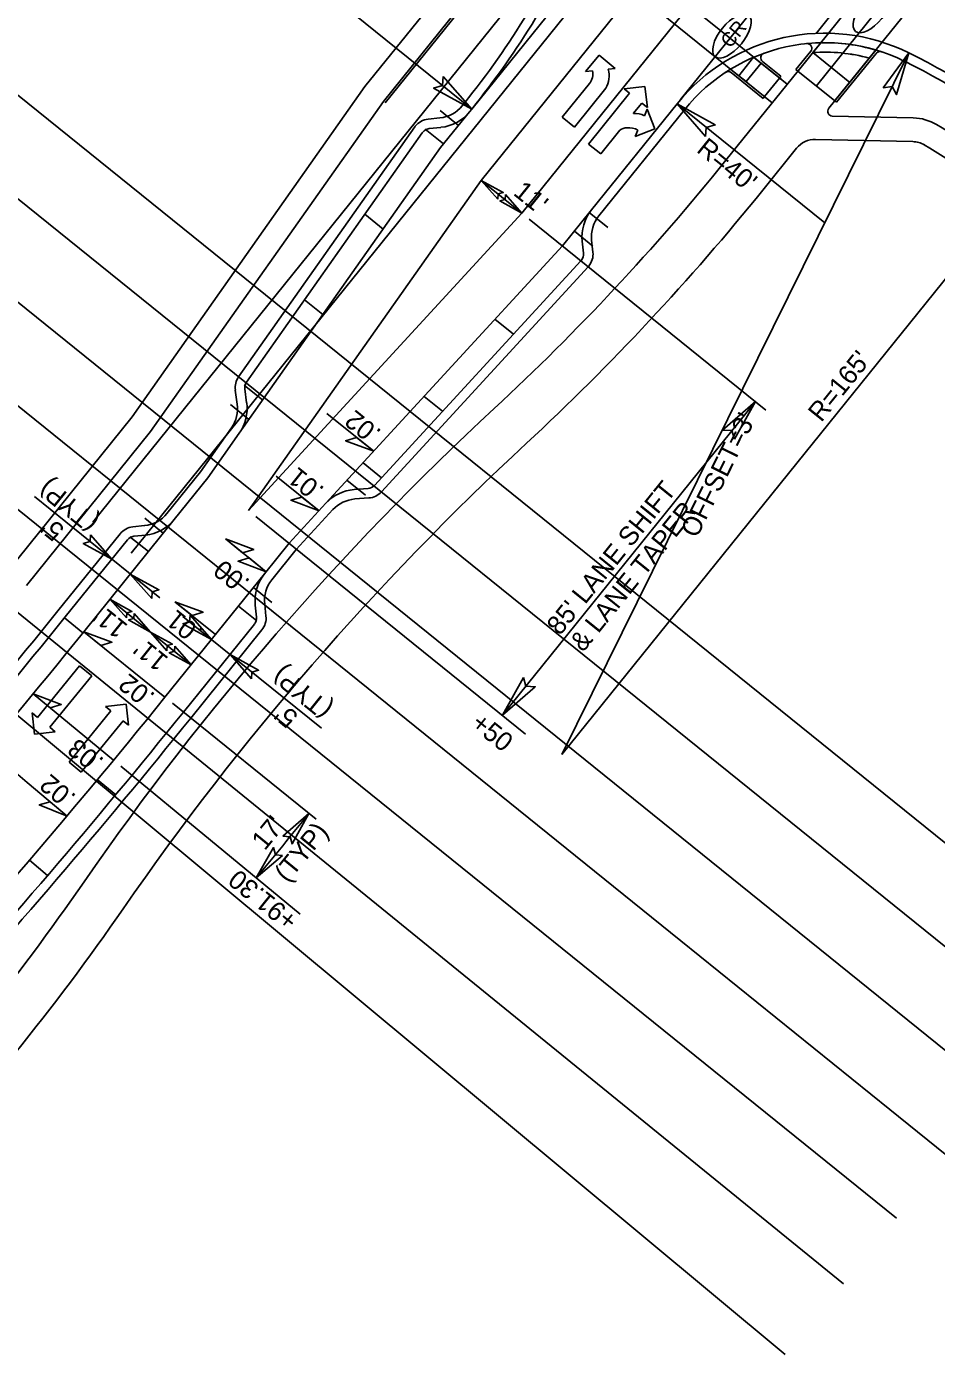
# Model space of a CAD drawing. Extents: x 1486489 to 1490134, y 497089 to 500876.
# Drawn here: x 1488552.5 to 1488744.4, y 498768.4 to 499048.4 of the extents above; entities that cross this region are included whole.
import ezdxf

# ---------------------------------------------------------------- set-up
doc = ezdxf.new("R2010")
doc.units = 0
for name, color, linetype in [('DEV PRELIMINARY STAMP CELL', 7, 'Continuous'), ('Gray Area Fill Shapes', 7, 'Continuous'), ('Pattern 5', 7, 'Continuous'), ('Prop DSN Text', 7, 'Continuous'), ('Prop Horizontal Alignment Station Label', 7, 'Continuous'), ('Prop North Arrow NAD83 for Plan Sheets CELL', 7, 'Continuous'), ('Prop Text', 7, 'Continuous'), ('Prop WCC CELL', 7, 'Continuous'), ('Scratch_Level_0', 7, 'Continuous'), ('Scratch_Level_5', 7, 'Continuous'), ('Sheet Block Revision CELL', 7, 'Continuous'), ('Sheet Block Title CELL', 7, 'Continuous'), ('Sheet Border Standard 30in CELL', 7, 'Continuous'), ('Sheet Cutting Line CELL', 7, 'Continuous'), ('Sheet Data Field CELL', 7, 'Continuous'), ('Sheet Plan CELL', 7, 'Continuous'), ('Sheet Plot Border Inside CELL', 7, 'Continuous'), ('Sheet Plot Border Outside CELL', 7, 'Continuous'), ('Sheet Sticker Exception Certification CELL', 7, 'Continuous'), ('Sheet Title CELL', 7, 'Continuous')]:
    doc.layers.add(name, color=color, linetype=linetype)

msp = doc.modelspace()

# ---------------------------------------------------------------- linework, layer by layer
at = {"layer": 'DEV PRELIMINARY STAMP CELL'}
for p, q in [((1488748.59, 499083.64), (1488718.98, 499046.92)), ((1488544.22, 498896.09), (1488552.63, 498889)), ((1488561.04, 498881.91), (1488552.63, 498889))]:
    msp.add_line(p, q, dxfattribs=at)
msp.add_lwpolyline([(1488561.04, 498881.91), (1488555.17, 498884.24), (1488557.51, 498884.89)], close=True, dxfattribs=at)
at = {"layer": 'Pattern 5'}
for p, q in [((1488719.96, 499044.95), (1488718.28, 499042.87)), ((1488730.19, 499041.71), (1488731.56, 499043.4))]:
    msp.add_line(p, q, dxfattribs=at)
for radius, start, end in [(38, 73.5472, 91.2616), (36, 74.8676, 94.0027)]:
    msp.add_arc((1488720.8, 499006.96), radius, start, end, dxfattribs=at)
at = {"layer": 'Prop DSN Text'}
msp.add_line((1488566.47, 498943.86), (1488817.57, 499255.22), dxfattribs=at)
at = {"layer": 'Prop Horizontal Alignment Station Label'}
for p, q in [((1488627.75, 499032.57), (1488666.32, 499080.39)), ((1488623.86, 499035.7), (1488655.57, 499075.03)), ((1488699.97, 499020.17), (1488719.96, 499044.95)), ((1488718.28, 499042.87), (1488726.07, 499036.59)), ((1488721.65, 499031.12), (1488731.56, 499043.4)), ((1488715.14, 499038.98), (1488722.93, 499032.7)), ((1488623.86, 499035.7), (1488574.78, 498966.09)), ((1488578.67, 498962.95), (1488627.75, 499032.57)), ((1488739.48, 499029.1), (1488722.4, 499029.49)), ((1488739.37, 499024.1), (1488718.87, 499024.57)), ((1488707.76, 499013.89), (1488714.87, 499022.71)), ((1488548.61, 498933.63), (1488574.78, 498966.09)), ((1488552.5, 498930.49), (1488578.67, 498962.95))]:
    msp.add_line(p, q, dxfattribs=at)
for centre, radius, start, end in [((1488720.8, 499006.96), 36, 74.8588, 94.0027), ((1488722.43, 499030.49), 1, 141.1156, 268.6989), ((1488739.26, 499019.1), 10, 59.261, 88.6989), ((1488665.4, 498894.91), 154.5, 51.1156, 59.261), ((1488718.76, 499019.57), 5, 88.6989, 141.1156), ((1488739.26, 499019.1), 5, 59.261, 88.6989), ((1488665.4, 498894.91), 149.5, 51.1156, 59.261), ((1488314.66, 499330.9), 495, 312.8235, 321.1156), ((1488314.66, 499330.9), 505, 312.8235, 321.1156), ((1489062.37, 498524.11), 605, 132.82346, 145.35373), ((1489062.37, 498524.11), 595, 132.82346, 145.35373), ((1488157.43, 499149.47), 495, 316.6966, 325.3537), ((1488157.43, 499149.47), 505, 316.6966, 325.3537)]:
    msp.add_arc(centre, radius, start, end, dxfattribs=at)
at = {"layer": 'Prop North Arrow NAD83 for Plan Sheets CELL'}
for p, q in [((1488628.14, 499032.25), (1488666.71, 499080.08)), ((1488714.75, 499039.29), (1488717.86, 499043.15)), ((1488723.32, 499032.39), (1488731.64, 499042.71)), ((1488715.14, 499038.98), (1488714.75, 499039.29)), ((1488722.93, 499032.7), (1488723.32, 499032.39))]:
    msp.add_line(p, q, dxfattribs=at)
for centre, start, end in [((1488717.08, 499043.77), 321.1156, 95.7599), ((1488732.42, 499042.09), 71.6856, 141.1156)]:
    msp.add_arc(centre, 1, start, end, dxfattribs=at)
at = {"layer": 'Prop Text'}
for p, q in [((1488755.33, 499088.81), (1488715.25, 499039.11)), ((1488723.04, 499032.83), (1488762.97, 499082.34)), ((1488711.66, 499037.18), (1488663.07, 499076.36)), ((1488709.75, 499032.29), (1488659.93, 499072.47))]:
    msp.add_line(p, q, dxfattribs=at)
at = {"layer": 'Prop WCC CELL'}
msp.add_ellipse((1488730.84, 499051.69), major_axis=(3.52, 4.36), ratio=0.462467, dxfattribs=at)
at = {"layer": 'Scratch_Level_0'}
for p, q in [((1488719.04, 499035.84), (1488758.98, 499085.37)), ((1488646.37, 499030.96), (1488600.96, 499067.58)), ((1488738.52, 499042.82), (1488665.4, 498894.91)), ((1488689.66, 499032.07), (1488720.8, 499006.96)), ((1488768.98, 499023.34), (1488665.4, 498894.91))]:
    msp.add_line(p, q, dxfattribs=at)
for points in [[(1488733.14, 499035.44), (1488738.52, 499042.82), (1488735.95, 499034), (1488735.02, 499035.74)], [(1488640.34, 499037.82), (1488646.37, 499030.96), (1488638.32, 499035.4), (1488640.22, 499035.92)], [(1488695.69, 499025.21), (1488689.66, 499032.07), (1488697.71, 499027.63), (1488695.81, 499027.11)]]:
    msp.add_lwpolyline(points, close=True, dxfattribs=at)
at = {"layer": 'Scratch_Level_5'}
for p, q in [((1488644.81, 499032.22), (1488644.37, 499031.66)), ((1488673.17, 499008.44), (1488691.22, 499030.81)), ((1488634.37, 499027.23), (1488634.48, 499027.36)), ((1488637.16, 499028.83), (1488639.66, 499029.1)), ((1488634.37, 499027.23), (1488597.22, 498974.53)), ((1488671.93, 499000.8), (1488671.66, 499003.3)), ((1488627.33, 498950.25), (1488670.91, 498997.68)), ((1488670.91, 498997.68), (1488671.06, 498997.86)), ((1488596.93, 498968.75), (1488596.52, 498971.68)), ((1488595.72, 498963.75), (1488589.18, 498954.47)), ((1488582.11, 498945.7), (1488589.18, 498954.47)), ((1488624.68, 498948.97), (1488621.73, 498948.75)), ((1488609.38, 498938.1), (1488617.1, 498946.5)), ((1488559.11, 498925.15), (1488572.22, 498941.4)), ((1488574.9, 498942.86), (1488577.4, 498943.13)), ((1488604.23, 498931.71), (1488609.38, 498938.1)), ((1488602.99, 498924.07), (1488602.72, 498926.57)), ((1488587.14, 498902.55), (1488602.12, 498921.13))]:
    msp.add_line(p, q, dxfattribs=at)
for centre, radius, start, end in [((1488506.26, 499143.96), 178, 321.1156, 336.027), ((1488720.8, 499006.96), 38, 63.6938, 141.1156), ((1488665.4, 498894.91), 163, 51.1156, 63.6938), ((1488638.92, 499036.06), 7, 276.1156, 321.1156), ((1488637.59, 499024.85), 4, 96.1156, 141.1156), ((1488678.62, 499004.04), 7, 141.1156, 186.1156), ((1488667.95, 499000.37), 4, 321.1156, 6.1156), ((1488600.49, 498972.23), 4, 144.8179, 187.9107), ((1488590, 498967.78), 7, 324.8179, 7.9107), ((1488624.38, 498952.96), 4, 274.3206, 317.4134), ((1488622.26, 498941.77), 7, 94.3206, 137.4134), ((1488576.66, 498950.09), 7, 276.1156, 321.1156), ((1488575.33, 498938.89), 4, 96.1156, 141.1156), ((1488609.68, 498927.32), 7, 141.1156, 186.1156), ((1487424.96, 499839.79), 1457, 317.71824, 321.11565), ((1488599.01, 498923.65), 4, 321.1156, 6.1156), ((1487424.96, 499839.79), 1493, 317.71734, 321.11565)]:
    msp.add_arc(centre, radius, start, end, dxfattribs=at)
at = {"layer": 'Sheet Block Revision CELL'}
for p, q in [((1488705.82, 499041.88), (1488702.68, 499037.99)), ((1488712.89, 499036.18), (1488705.82, 499041.88)), ((1488707.38, 499040.63), (1488705.82, 499041.88)), ((1488709.75, 499032.29), (1488700.96, 499039.37)), ((1488707.81, 499033.21), (1488701.08, 499038.64)), ((1488707.38, 499040.63), (1488704.24, 499036.74)), ((1488704.24, 499036.74), (1488707.38, 499040.63)), ((1488711.58, 499037.88), (1488707.69, 499041.02)), ((1488702.68, 499037.99), (1488704.24, 499036.74)), ((1488711.27, 499037.49), (1488708.13, 499033.6)), ((1488711.27, 499037.49), (1488711.58, 499037.88)), ((1488708.13, 499033.6), (1488707.81, 499033.21))]:
    msp.add_line(p, q, dxfattribs=at)
for centre, start, end in [((1488708.32, 499041.79), 109.7013, 231.1156), ((1488700.45, 499037.86), 51.1156, 123.3611)]:
    msp.add_arc(centre, 1, start, end, dxfattribs=at)
msp.add_ellipse((1488701.24, 499046.37), major_axis=(3.52, 4.36), ratio=0.462467, dxfattribs=at)
at = {"layer": 'Sheet Block Title CELL'}
for p, q in [((1488646.37, 499030.96), (1488732.3, 499137.52)), ((1488690.38, 499032.96), (1488772.04, 499134.22)), ((1488648.38, 499015.93), (1488739.4, 499128.8)), ((1488656.94, 499009.02), (1488754.24, 499129.68)), ((1488639.82, 499022.84), (1488645.92, 499030.41)), ((1488639.82, 499022.84), (1488597.35, 498962.6)), ((1488599.3, 498946.31), (1488648.38, 499015.93)), ((1488656.94, 499009.02), (1488599.3, 498946.31)), ((1488623.8, 499008.77), (1488627.69, 499005.64)), ((1488665.51, 499002.12), (1488671.61, 499009.69)), ((1488615.63, 498947.86), (1488665.51, 499002.12)), ((1488611.1, 498990.76), (1488614.99, 498987.62)), ((1488651.26, 498986.63), (1488655.16, 498983.49)), ((1488636.35, 498970.39), (1488640.24, 498967.26)), ((1488564.56, 498920.76), (1488583.66, 498944.44)), ((1488581.69, 498906.95), (1488602.67, 498932.97)), ((1488560.48, 498923.67), (1488564.38, 498920.53)), ((1488567.45, 498889.57), (1488571.3, 498886.37)), ((1488553.15, 498872.63), (1488556.95, 498869.38))]:
    msp.add_line(p, q, dxfattribs=at)
for radius, start in [(1464, 317.34346), (1486, 317.34959)]:
    msp.add_arc((1487424.96, 499839.79), radius, start, 321.11565, dxfattribs=at)
at = {"layer": 'Sheet Border Standard 30in CELL'}
for p, q in [((1488639.69, 499030.64), (1488643.58, 499027.51)), ((1488636.55, 499026.75), (1488640.45, 499023.61)), ((1488671.15, 499009.13), (1488675.05, 499005.99)), ((1488668.02, 499005.23), (1488671.91, 499002.09)), ((1488598.4, 498972.74), (1488602.29, 498969.6)), ((1488595.51, 498968.64), (1488599.4, 498965.5)), ((1488623.46, 498956.38), (1488627.35, 498953.24)), ((1488620.07, 498952.69), (1488623.96, 498949.55)), ((1488577.43, 498944.68), (1488581.32, 498941.54)), ((1488574.29, 498940.79), (1488578.18, 498937.65)), ((1488600.33, 498930.07), (1488604.22, 498926.93)), ((1488597.19, 498926.17), (1488601.09, 498923.04))]:
    msp.add_line(p, q, dxfattribs=at)
at = {"layer": 'Sheet Cutting Line CELL'}
for p, q in [((1488656.94, 499009.02), (1488648.38, 499015.93)), ((1488708.42, 498967.51), (1488658.5, 499007.77)), ((1488652.83, 498903.14), (1488706.19, 498969.31)), ((1488554.15, 498949.25), (1488580.58, 498927.93)), ((1488600.86, 498945.06), (1488657.72, 498899.2)), ((1488578.64, 498920.69), (1488570.08, 498927.6)), ((1488585.48, 498923.97), (1488614.68, 498900.43)), ((1488587.2, 498913.79), (1488578.64, 498920.69))]:
    msp.add_line(p, q, dxfattribs=at)
at = {"layer": 'Sheet Data Field CELL'}
for p, q in [((1488615.81, 498966.78), (1488625.7, 498958.81)), ((1488605.14, 498953.55), (1488614.17, 498946.27)), ((1488594.47, 498940.32), (1488603.03, 498933.41)), ((1488583.8, 498927.09), (1488592.36, 498920.18)), ((1488564.56, 498920.76), (1488581.69, 498906.95)), ((1488553.9, 498907.68), (1488570.86, 498893.68)), ((1488583.24, 498905.69), (1488613.6, 498881.21)), ((1488572.4, 498892.4), (1488610.19, 498861.21))]:
    msp.add_line(p, q, dxfattribs=at)
for points in [[(1488625.7, 498958.81), (1488619.77, 498961.02), (1488622.1, 498961.71)], [(1488614.17, 498946.27), (1488608.25, 498948.48), (1488610.57, 498949.17)], [(1488594.47, 498940.32), (1488600.39, 498938.11), (1488598.07, 498937.42)], [(1488603.03, 498933.41), (1488597.11, 498935.62), (1488599.43, 498936.32)], [(1488583.8, 498927.09), (1488589.72, 498924.88), (1488587.4, 498924.18)], [(1488564.56, 498920.76), (1488570.49, 498918.55), (1488568.16, 498917.85)], [(1488553.9, 498907.68), (1488559.8, 498905.41), (1488557.46, 498904.74)], [(1488606.56, 498877.64), (1488612.05, 498882.47), (1488608.5, 498876.03), (1488608.08, 498877.55)], [(1488606.47, 498873.61), (1488600.93, 498868.85), (1488604.55, 498875.25), (1488604.96, 498873.72)]]:
    msp.add_lwpolyline(points, close=True, dxfattribs=at)
msp.add_arc((1487424.96, 499839.79), 1525, 320.45522, 321.11565, dxfattribs=at)
at = {"layer": 'Sheet Plan CELL'}
for p, q in [((1488574.59, 498937.3), (1488825.69, 499248.67)), ((1488778.61, 498850.05), (1488467.24, 499101.15)), ((1488456.57, 499087.92), (1488767.94, 498836.82)), ((1488757.26, 498823.59), (1488445.9, 499074.69)), ((1488435.23, 499061.45), (1488746.59, 498810.35)), ((1488735.92, 498797.12), (1488424.55, 499048.22)), ((1488414.36, 499035.59), (1488724.76, 498783.3)), ((1488712.49, 498768.39), (1488405.02, 499024.24))]:
    msp.add_line(p, q, dxfattribs=at)
at = {"layer": 'Sheet Plot Border Inside CELL'}
for p, q in [((1488673.25, 499042.32), (1488670.38, 499038.85)), ((1488676.64, 499039.52), (1488673.25, 499042.32)), ((1488670.38, 499038.85), (1488671.86, 499039.01)), ((1488675.16, 499039.36), (1488676.64, 499039.52)), ((1488671.19, 499036.34), (1488665.44, 499029.22)), ((1488668.01, 499027.14), (1488674.63, 499035.36)), ((1488671.01, 499023.57), (1488679.67, 499034.31)), ((1488678.51, 499035.25), (1488682.9, 499035.69)), ((1488679.67, 499034.31), (1488678.51, 499035.25)), ((1488682.9, 499035.69), (1488683.41, 499031.3)), ((1488682.24, 499032.24), (1488680.45, 499030.02)), ((1488683.41, 499031.3), (1488682.24, 499032.24)), ((1488682.78, 499029.56), (1488683.38, 499030.94)), ((1488683.38, 499030.94), (1488684.99, 499026.81)), ((1488665.44, 499029.22), (1488668.01, 499027.14)), ((1488677.63, 499026.52), (1488673.58, 499021.5)), ((1488684.99, 499026.81), (1488680.86, 499025.19)), ((1488680.86, 499025.19), (1488681.43, 499026.53)), ((1488673.58, 499021.5), (1488671.01, 499023.57)), ((1488554.83, 498902.7), (1488563.69, 498913.55)), ((1488563.69, 498913.55), (1488566.24, 498911.46)), ((1488566.24, 498911.46), (1488557.39, 498900.61)), ((1488569.14, 498905.03), (1488573.53, 498905.51)), ((1488570.3, 498904.08), (1488569.14, 498905.03)), ((1488573.53, 498905.51), (1488574.02, 498901.04)), ((1488554.16, 498899.18), (1488553.67, 498903.65)), ((1488553.67, 498903.65), (1488554.83, 498902.7)), ((1488561.45, 498893.23), (1488570.3, 498904.08)), ((1488572.86, 498901.99), (1488564.01, 498891.15)), ((1488574.02, 498901.04), (1488572.86, 498901.99)), ((1488558.55, 498899.66), (1488554.16, 498899.18)), ((1488557.39, 498900.61), (1488558.55, 498899.66)), ((1488564.01, 498891.15), (1488561.45, 498893.23))]:
    msp.add_line(p, q, dxfattribs=at)
for centre, radius, start, end in [((1488668.66, 499038.39), 3.27, 321.1156, 10.7738), ((1488670.11, 499037.99), 5.25, 329.7917, 15.1034), ((1488680.74, 499025.61), 4.43, 62.7065, 93.5851), ((1488679.13, 499024.49), 2.52, 90.1888, 126.5008), ((1488679.4, 499022.59), 4.43, 62.8253, 93.6789)]:
    msp.add_arc(centre, radius, start, end, dxfattribs=at)
at = {"layer": 'Sheet Plot Border Outside CELL'}
for points in [[(1488651.85, 499011.99), (1488648.38, 499015.93), (1488653.01, 499013.38), (1488651.92, 499013.08)], [(1488653.47, 499012.97), (1488656.94, 499009.02), (1488652.31, 499011.58), (1488653.41, 499011.88)], [(1488701.75, 498961.33), (1488706.19, 498969.31), (1488699.26, 498963.27), (1488701.23, 498963.16)], [(1488565.96, 498941.21), (1488570.49, 498936.07), (1488564.45, 498939.4), (1488565.88, 498939.79)], [(1488578.9, 498927.79), (1488574.38, 498932.93), (1488580.42, 498929.6), (1488578.99, 498929.21)], [(1488573.55, 498923.66), (1488570.08, 498927.6), (1488574.71, 498925.05), (1488573.62, 498924.75)], [(1488575.17, 498924.63), (1488578.64, 498920.69), (1488574.01, 498923.24), (1488575.11, 498923.54)], [(1488586.98, 498924.26), (1488591.5, 498919.12), (1488585.47, 498922.45), (1488586.89, 498922.84)], [(1488582.11, 498916.75), (1488578.64, 498920.69), (1488583.27, 498918.14), (1488582.18, 498917.84)], [(1488583.74, 498917.73), (1488587.2, 498913.79), (1488582.58, 498916.34), (1488583.67, 498916.64)], [(1488599.92, 498910.84), (1488595.4, 498915.98), (1488601.43, 498912.65), (1488600.01, 498912.26)], [(1488657.27, 498911.12), (1488652.83, 498903.14), (1488659.76, 498909.18), (1488657.79, 498909.29)]]:
    msp.add_lwpolyline(points, close=True, dxfattribs=at)
at = {"layer": 'Sheet Sticker Exception Certification CELL'}
for p, q in [((1488646.37, 499030.96), (1488645.92, 499030.41)), ((1488671.61, 499009.69), (1488689.66, 499032.07)), ((1488635.93, 499025.97), (1488598.85, 498973.38)), ((1488635.93, 499025.97), (1488636.03, 499026.11)), ((1488637.38, 499026.84), (1488639.88, 499027.11)), ((1488669.94, 499000.58), (1488669.67, 499003.08)), ((1488625.85, 498951.61), (1488669.4, 498998.98)), ((1488669.4, 498998.98), (1488669.5, 498999.11)), ((1488598.91, 498969.02), (1488598.5, 498971.95)), ((1488597.35, 498962.6), (1488590.74, 498953.22)), ((1488583.66, 498944.44), (1488590.74, 498953.22)), ((1488624.53, 498950.96), (1488621.58, 498950.74)), ((1488607.87, 498939.41), (1488615.63, 498947.86)), ((1488575.12, 498940.88), (1488577.62, 498941.14)), ((1488560.67, 498923.9), (1488573.77, 498940.14)), ((1488602.67, 498932.97), (1488607.87, 498939.41)), ((1488601, 498923.86), (1488600.73, 498926.36)), ((1488585.58, 498903.81), (1488600.57, 498922.39))]:
    msp.add_line(p, q, dxfattribs=at)
for centre, radius, start, end in [((1488506.26, 499143.96), 180, 321.1156, 336.027), ((1488720.8, 499006.96), 40, 63.6938, 141.1156), ((1488665.4, 498894.91), 165, 51.1156, 63.6938), ((1488638.92, 499036.06), 9, 276.1156, 321.1156), ((1488637.59, 499024.85), 2, 96.1156, 141.1156), ((1488678.62, 499004.04), 9, 141.1156, 186.1156), ((1488667.95, 499000.37), 2, 321.1156, 6.1156), ((1488600.49, 498972.23), 2, 144.8179, 187.9107), ((1488590, 498967.78), 9, 324.8179, 7.9107), ((1488622.26, 498941.77), 9, 94.3206, 137.4134), ((1488624.38, 498952.96), 2, 274.3206, 317.4134), ((1488576.66, 498950.09), 9, 276.1156, 321.1156), ((1488575.33, 498938.89), 2, 96.1156, 141.1156), ((1488609.68, 498927.32), 9, 141.1156, 186.1156), ((1487424.96, 499839.79), 1459, 317.71824, 321.11565), ((1488599.01, 498923.65), 2, 321.1156, 6.1156), ((1487424.96, 499839.79), 1491, 317.71734, 321.11565)]:
    msp.add_arc(centre, radius, start, end, dxfattribs=at)

# ---------------------------------------------------------------- texts
at = {"layer": 'Gray Area Fill Shapes'}
msp.add_text('.02', height=4, rotation=139.8642, dxfattribs=at).set_placement((1488563.16, 498886.19))
at = {"layer": 'Scratch_Level_0'}
for s, rotation, p in [("R=40'", 321.1156, (1488693.57, 499022.08)), ("R=165'", 51.1156, (1488720.08, 498964.76)), ("OFFSET=3'", 63.6938, (1488693.84, 498940.32))]:
    msp.add_text(s, height=4, rotation=rotation, dxfattribs=at).set_placement(p)
at = {"layer": 'Sheet Block Revision CELL'}
msp.add_text('CR', height=3, rotation=51.1156, dxfattribs=at).set_placement((1488700.91, 499043.61))
at = {"layer": 'Sheet Data Field CELL'}
for s, rotation, p in [('.02', 141.1755, (1488627.54, 498963.07)), ('.01', 141.1755, (1488615.51, 498951)), ('.00', 141.1755, (1488599.83, 498931.51)), ('.01', 141.1755, (1488589.9, 498920.95)), ('.02', 141.1755, (1488579.83, 498907.5)), ('.03', 141.1755, (1488569.05, 498893.82)), ("17'", 50.7918, (1488602.73, 498874.46)), ('(TYP)', 50.7918, (1488607.53, 498867.68)), ('+91.30', 141.1755, (1488610.02, 498860.53))]:
    msp.add_text(s, height=4, rotation=rotation, dxfattribs=at).set_placement(p)
at = {"layer": 'Sheet Title CELL'}
for s, rotation, p in [("11'", 321.1156, (1488654.93, 499013.01)), ('(TYP)', 141.1156, (1488568.02, 498944.47)), ("85' LANE SHIFT", 51.1156, (1488664.97, 498919.79)), ('& LANE TAPER', 51.1156, (1488669.87, 498916.31)), ("5'", 141.1156, (1488560.75, 498942.63)), ("11'", 141.1156, (1488574.08, 498922.09)), ("11'", 141.1156, (1488582.64, 498915.19)), ('(TYP)', 141.1156, (1488617.32, 498905.07)), ("5'", 141.1156, (1488610.05, 498903.23)), ('+50', 321.1156, (1488645.94, 498900.89))]:
    msp.add_text(s, height=4, rotation=rotation, dxfattribs=at).set_placement(p)

doc.saveas('drawing.dxf')
